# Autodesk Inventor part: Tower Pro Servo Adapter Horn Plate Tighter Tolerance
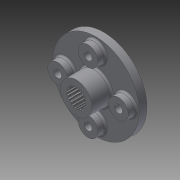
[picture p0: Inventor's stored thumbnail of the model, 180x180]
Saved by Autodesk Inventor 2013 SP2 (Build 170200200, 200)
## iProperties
Created: 2020-02
Part Number: Tower Pro Servo Adapter Horn Plate Tighter Tolerance
Material: Generic
Document SubType Name: Modeling
Designer: DELL
Density: 1 g/cm^3
Author: DELL
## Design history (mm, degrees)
sketch "Sketch1"
  geometry: C1 r 4 at (0, 0); C2 r 2.183 at (0, 0); 1 further point
  constraints: 2 centre point, 2 coincident
  dimensions: "d3" = 8 diameter of C1; "d8" = 4.367 diameter of C2
extrude "Extrusion1" new body sketch "Sketch1" distance "d4" = 5; taper "d5" = 0 deg
sketch "Sketch5"
  geometry: C1 r 2.183 at (0, 0) reference; 1 further point
extrude "Extrusion4" join sketch "Sketch5" distance "d32" = 1.5; taper "d33" = 0 deg
sketch "Sketch3"
  geometry: C1 r 11 at (0, 0); 1 further point
  constraints: 1 centre point, 1 coincident
  dimensions: "d21" = 22 diameter of C1
extrude "Extrusion3" join sketch "Sketch3" distance "d23" = 2; taper "d24" = 0 deg
sketch "Sketch4"
  geometry: 2 further points
  constraints: 1 coincident
hole "Hole1" sketch "Sketch4" at (0, 0) diameter "d25" = 2.8; stored, may be unused: countersink angle "d29" = 90 deg, drill point angle "d31" = 0 deg; dims "d26" = 6, "d27" = 5, "d28" = 1.75, "d30" = 4
sketch "Sketch6" dims "d37" = 15.5
  geometry: C1 r 2.5 at (7.75, 0); 2 further points
  constraints: 2 horizontal alignment, 1 centre point, 1 coincident, 2 other
  dimensions: "d39" = 5 diameter of C1
extrude "Extrusion5" join sketch "Sketch6" distance "d40" = 2; taper "d41" = 0 deg
sketch "Sketch7"
  geometry: C1 r 2.5 at (0, 0) reference; 2 further points
  constraints: 1 coincident
hole "Hole2" sketch "Sketch7" at (0, 0) diameter "d42" = 2; stored, may be unused: countersink angle "d46" = 90 deg, drill point angle "d48" = 118 deg; dims "d43" = 6, "d44" = 6.5, "d45" = 1, "d47" = 2
pattern_circular "Circular Pattern2" dims angle "d50" = 360 deg
fillet "Fillet1" dims "d52" = 0.5
feature "Sculpt1"
sketch "Sketch8"
  geometry: A1 r 0.062 centre (0.316, 2.224) between (0.258, 2.201) and (0.303, 2.162); A2 r 1.016 centre (-0.691, 1.839) between (0.258, 2.201) and (0.243, 2.237); A3 r 2.475 centre (0, 0) between (0.102, 2.473) and (-0.102, 2.473); A4 r 1.016 centre (0.691, 1.839) between (-0.243, 2.237) and (-0.258, 2.201); A5 r 0.062 centre (-0.316, 2.224) between (-0.303, 2.162) and (-0.258, 2.201); A6 r 2.183 centre (0, 0) between (0.303, 2.162) and (-0.303, 2.162)
  constraints: 12 point on circle, 6 centre point, 1 coincident, 6 other
  dimensions: "d53" = 2.475 radius of A3; "d54" = 2.1835 radius of A6
sketch "Sketch9"
  geometry: L1 (0, -15.4)-(0, 15.4) reference; L2 (-0.143, 2.465)-(-0.096, 2.529); L3 (-0.332, 2.144)-(-0.297, 2.213); L4 (0.143, 2.465)-(0.096, 2.529); L5 (0.332, 2.144)-(0.297, 2.213); A1 r 0.075 centre (-0.385, 2.205) between (-0.372, 2.131) and (-0.314, 2.179); A2 r 2.163 centre (0, 0) between (-0.372, 2.131) and (0.372, 2.131); A3 r 1.544 centre (1.121, 1.577) between (-0.1, 2.523) and (-0.138, 2.471); A4 r 2.481 centre (1.885, 1.03) between (-0.3, 2.206) and (-0.329, 2.151); A5 r 2.5 centre (0, 0) between (0.119, 2.497) and (-0.119, 2.497); A6 r 1.544 centre (-1.121, 1.577) between (0.138, 2.471) and (0.1, 2.523); A7 r 2.481 centre (-1.885, 1.03) between (0.329, 2.151) and (0.3, 2.206); A8 r 0.075 centre (0.385, 2.205) between (0.314, 2.179) and (0.372, 2.131); A9 r 2.163 centre (0, 0) between (0.372, 2.131) and (-0.372, 2.131); 1 further point
  constraints: 14 point on circle, 14 symmetric about line, 9 centre point, 8 end point, 7 midpoint, 2 concentric, 1 coincident, 1 tangent, 16 other
  dimensions: "d62" = 4.327 diameter of A2; "d70" = 0.385 distance from line of L1 A1.centre; "d71" = 2.20549 vertical distance of A1.centre point (0, 0); "d72" = 2.5 radius of A5; "d73" = 0.385 distance from line of A8.centre L1 (derived); "d74" = 0.07547 radius of A1; "d75" = 0.11947 distance from line of A5.end L1; "d76" = 0.11947 distance from line of A5.start L1 (derived)
body "Solid1"
feature "Composite1"
body "Srf1"
other parameters: "d59" = 5
